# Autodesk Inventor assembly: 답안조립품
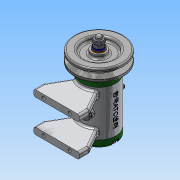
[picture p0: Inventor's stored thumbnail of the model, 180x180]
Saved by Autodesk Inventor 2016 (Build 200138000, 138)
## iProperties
Created: 2018-05
Part Number: 답안조립품
Material: 일반
Document SubType Name: Assembly
Designer: Administrator
Author: Administrator
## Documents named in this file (16)
- C:\Users\Administrator\Desktop\480507V1022\답안조립품.iam
- C:\Users\Administrator\Desktop\480507V1022\V벨트풀리.ipt
- C:\Users\Administrator\Desktop\480507V1022\너트 M8.ipt
- C:\Users\Administrator\Desktop\480507V1022\니플 M6x0.75.ipt
- C:\Users\Administrator\Desktop\480507V1022\뒤커버.ipt
- C:\Users\Administrator\Desktop\480507V1022\베어링 6002.ipt
- C:\Users\Administrator\Desktop\480507V1022\본체.ipt
- C:\Users\Administrator\Desktop\480507V1022\볼트 M4x12.ipt
- C:\Users\Administrator\Desktop\480507V1022\볼트 M6x8.ipt
- C:\Users\Administrator\Desktop\480507V1022\스프링와셔 8.ipt
- C:\Users\Administrator\Desktop\480507V1022\앞커버.ipt
- C:\Users\Administrator\Desktop\480507V1022\오일 실 15 25 7.ipt
- C:\Users\Administrator\Desktop\480507V1022\와셔 6x11.5.ipt
- C:\Users\Administrator\Desktop\480507V1022\와셔 8x17.ipt
- C:\Users\Administrator\Desktop\480507V1022\축.ipt
- C:\Users\Administrator\Desktop\480507V1022\키 3x3x12.ipt
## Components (1 placed, 1 different names)
1. V벨트풀리:2
